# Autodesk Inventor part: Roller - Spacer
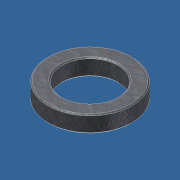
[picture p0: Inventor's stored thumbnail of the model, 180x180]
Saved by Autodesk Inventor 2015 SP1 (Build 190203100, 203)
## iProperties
Category: Mechanical Engineering Drawing and Design - CADD
Manager: Fábio Ricardo de Oliveira Souza
Company: SENAI - Serviço Nacional de Aprendizagem Industrial
Created: 2011-06
Part Number: Roller - Spacer
Material: Steel
Description: Steel - DIN-20CrMoS4
Document SubType Name: Modeling
Designer: Guilherme Augusto Franco de Souza
Engineer: George Geraldo de Oliveia Silva
Authority: Fábio Ricardo de Oliveira Soza
Density: 7.85 g/cm^3
Mass: 2.28735 g
Surface Area: 4.13566 cm^2
Volume: 0.291383 cm^3
Appearance: Machined 02
Subject: WorldSkill 2011 - London, England
Author: Guilherme Augusto Franco de Souza
Revision Number: 00
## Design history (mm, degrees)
sketch "Sketch2"
  geometry: C1 r 5 at (0, 0); C2 r 7.5 at (0, 0); 1 further point
  constraints: 2 centre point, 2 coincident
  dimensions: "d2" = 10 diameter of C1; "d3" = 15 diameter of C2
extrude "Extrusion2" new body sketch "Sketch2" stored distance "d4" = 3; taper "d5" = 0 deg
chamfer "Chamfer1" distance "d6" = 0.2; stored, may be unused: second distance "d7" = 2, angle "d8" = 45 deg
body "Solid2"
